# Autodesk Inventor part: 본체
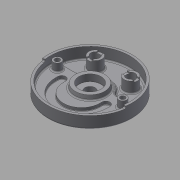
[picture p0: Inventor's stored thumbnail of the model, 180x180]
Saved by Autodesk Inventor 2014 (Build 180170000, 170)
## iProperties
Created: 2015-06
Part Number: 본체
Material: Generic
Document SubType Name: Modeling
Designer: MYHOME
Mass: 397.535 g
Surface Area: 1043.28 cm^2
Volume: 397.535 cm^3
Density: 1 g/cm^3
Appearance: Default
Author: MYHOME
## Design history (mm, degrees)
sketch "스케치1"
  geometry: C1 r 95 at (0, 0); 1 further point
  constraints: 1 centre point, 1 coincident
  dimensions: "d0" = 190 diameter of C1
extrude "돌출1" new body sketch "스케치1" distance "d1" = 32; taper "d2" = 0 deg
sketch "스케치2"
  geometry: C1 r 95 at (0, 0) reference; C2 r 90 at (0, 0)
  constraints: 1 centre point, 1 coincident
  dimensions: "d3" = 180 diameter of C2
extrude "돌출2" cut sketch "스케치2" distance "d4" = 25; taper "d5" = 0 deg
sketch "스케치3"
  geometry: L1 (-88.566, 16)-(88.566, 16); C1 r 42 at (0, 0); A1 r 90 centre (0, 0) between (-88.566, 16) and (88.566, 16) reference
  constraints: 2 end point, 2 point on circle, 1 centre point, 1 coincident, 1 horizontal
  dimensions: "d6" = 84 diameter of C1; "d7" = 16 distance from line of L1 C1.centre
extrude "돌출3" join sketch "스케치3" distance "d8" = 7; taper "d9" = 0 deg
sketch "스케치4"
  geometry: L1 (88.566, 16)-(38.833, 16) reference; L2 (-50, -19)-(-50, -14); L3 (50, -19)-(50, -14); L4 (59, -19)-(59, -14); L5 (41, -19)-(41, -14); L6 (-41, -19)-(-41, -14); L7 (-59, -19)-(-59, -14); A1 r 90 centre (0, 0) between (-88.566, 16) and (88.566, 16) reference; A2 r 50 centre (0, -19) between (-50, -19) and (50, -19); A3 r 59 centre (0, -19) between (-59, -19) and (59, -19); A4 r 41 centre (0, -19) between (-41, -19) and (41, -19); A5 r 9 centre (-50, -19) between (-41, -19) and (-59, -19); A6 r 9 centre (50, -19) between (59, -19) and (41, -19); A7 r 9 centre (-50, -14) between (-41, -14) and (-41, -14); A8 r 9 centre (50, -14) between (59, -14) and (41, -14); 1 further point
  constraints: 16 point on circle, 12 end point, 9 tangent, 7 centre point, 2 coincident, 2 horizontal alignment, 2 parallel, 1 perpendicular, 1 vertical alignment
  dimensions: "d10" = 19 distance of A2.centre A1.centre; "d11" = 5 distance of L2.start L2.end; "d12" = 5 distance of L3.start L3.end; "d13" = 18 radial gap between concentric circles of A3 A4; "d14" = 41 radius of A4; "d15" = 18 diameter of A7; "d16" = 18 diameter of A8
extrude "돌출4" cut sketch "스케치4" distance "d17" = 7; taper "d18" = 0 deg
fillet "모깎기1" dims "d20" = 10
sketch "스케치6"
  geometry: C1 r 95 at (0, 0) reference; C2 r 26 at (0, 0)
  constraints: 1 centre point, 1 coincident
  dimensions: "d21" = 52 diameter of C2
extrude "돌출5" join sketch "스케치6" distance "d22" = 12; taper "d23" = -15 deg
sketch "스케치7"
  geometry: L1 (0, 0)-(-94.075, -13.221); L2 (0, 0)-(94.075, -13.221); L3 (-95, 0)-(95, 0); C1 r 90 at (0, 0) reference; A1 r 95 centre (0, 0) between (-95, 0) and (95, 0) reference; 1 further point
  constraints: 6 end point, 4 point on circle, 1 coincident, 1 horizontal, 1 midpoint
  dimensions: "d24" = 8 deg angle of L1 L3; "d25" = 8 deg angle of L2 L3
extrude "돌출6" cut sketch "스케치7" distance "d26" = 5; taper "d27" = 0 deg
fillet "모깎기2" dims "d28" = 3
sketch "스케치8"
  geometry: C1 r 9 at (-74, 0); C2 r 9 at (74, 0); A1 r 90 centre (0, 0) between (-85.114, 29.25) and (85.114, 29.25) reference
  constraints: 2 centre point, 2 horizontal alignment
  dimensions: "d29" = 18 diameter of C1; "d30" = 18 diameter of C2; "d31" = 148 distance of C2.centre C1.centre; "d32" = 74 distance of C2.centre A1.centre
extrude "돌출7" join sketch "스케치8" stored distance "d33" = 5; taper "d34" = 0 deg
sketch "스케치9"
  geometry: C1 r 9 at (74, 0) reference; C2 r 9 at (-74, 0) reference; 2 further points
  constraints: 2 coincident
hole "구멍1" sketch "스케치9" at (-74, 0), (74, 0) diameter "d35" = 11; stored, may be unused: countersink angle "d39" = 90 deg, drill point angle "d41" = 0 deg; dims "d36" = 6, "d37" = 18, "d38" = 11, "d40" = 8
sketch "스케치10"
  geometry: C1 r 35 at (0, 0); A1 r 42 centre (0, 0) between (36.373, 21) and (-36.373, 21) reference
  constraints: 1 centre point, 1 coincident
  dimensions: "d42" = 70 diameter of C1
extrude "돌출8" join sketch "스케치10" distance "d43" = 10; taper "d44" = -10 deg
hole "구멍2" diameter "d47" = 23; stored, may be unused: countersink angle "d51" = 90 deg, drill point angle "d53" = 0 deg; dims "d45" = 10, "d46" = 10, "d48" = 6, "d49" = 50, "d50" = 15, "d52" = 8
sketch "스케치11"
  geometry: C1 r 15 at (-40, 52); C2 r 15 at (40, 52); C3 r 10 at (-40, 52); C4 r 10 at (40, 52); A1 r 90 centre (0, 0) between (85.114, 29.25) and (-85.114, 29.25) reference
  constraints: 4 centre point, 2 coincident, 1 horizontal alignment
  dimensions: "d54" = 52 vertical distance of A1.centre C1.centre; "d55" = 80 distance of C2.centre C1.centre; "d56" = 40 horizontal distance of C2.centre A1.centre; "d57" = 30 diameter of C1; "d58" = 30 diameter of C2; "d59" = 20 diameter of C3; "d60" = 20 diameter of C4
extrude "돌출9" join sketch "스케치11" stored distance "d61" = 10; taper "d62" = 0 deg
sketch "스케치12"
  geometry: C1 r 10 at (0, 0) reference; C2 r 10 at (80, 0) reference; 1 further point
extrude "돌출10" cut sketch "스케치12" stored distance "d63" = 10; taper "d64" = 0 deg
sketch "스케치13"
  geometry: C1 r 95 at (0, 0) reference; C2 r 68 at (0, 0)
  constraints: 1 centre point, 1 coincident, 1 other
  dimensions: "d65" = 136 diameter of C2
feature "엠보싱1" sketch "스케치13" dims "d66" = 0.5, "d67" = 0
fillet "모깎기3" dims "d68" = 3
fillet "모깎기4" dims "d69" = 3
fillet "모깎기5" dims "d70" = 1
fillet "모깎기6" dims "d71" = 3
fillet "모깎기7" dims "d72" = 3
fillet "모깎기8" dims "d73" = 0.3
fillet "모깎기9" dims "d74" = 3
sketch "스케치14"
  geometry: L1 (-6, 13.748)-(-6, -13.748); L2 (6, 13.748)-(6, -13.748); L3 (66.252, 6)-(93.748, 6); L4 (66.252, -6)-(93.748, -6); C1 r 10 at (0, 0) reference; C2 r 10 at (80, 0) reference; A1 r 15 centre (0, 0) between (6, 13.748) and (-6, 13.748) reference; A2 r 15 centre (80, 0) between (93.748, 6) and (93.748, -6) reference; 1 further point
  constraints: 8 end point, 8 point on circle, 2 parallel, 1 perpendicular, 1 vertical
  dimensions: "d75" = 12 distance between parallel lines of L2 L1; "d78" = 6 distance from line of L2 C1.centre; "d80" = 12 distance between parallel lines of L4 L3; "d81" = 6 distance from line of L3 A2.centre
extrude "돌출11" cut sketch "스케치14" distance "d82" = 3; taper "d83" = 0 deg
node "솔리드1"
node "투영된 루프1"
node "투영된 루프2"
node "투영된 루프3"
node "투영된 루프4"
